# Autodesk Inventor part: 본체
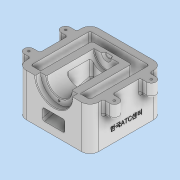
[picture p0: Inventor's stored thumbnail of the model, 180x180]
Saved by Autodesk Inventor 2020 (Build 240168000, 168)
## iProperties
Created: 2022-03
Part Number: 본체
Material: 일반
Document SubType Name: Modeling
Designer: Administrator
Density: 1 g/cm^3
Appearance: 기본값
Author: Administrator
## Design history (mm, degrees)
sketch "스케치1"
  geometry: L1 (55, 55)-(-55, 55); L2 (-55, 55)-(-55, -55); L3 (-55, -55)-(55, -55); L4 (55, -55)-(55, 55); L5 (55, 55)-(-55, -55); L6 (-55, 55)-(55, -55); 1 further point
  constraints: 12 end point, 2 midpoint, 2 parallel, 1 horizontal, 1 perpendicular
  dimensions: "d0" = 110 distance of L3.end L1.start; "d1" = 110 distance of L1.start L1.end
extrude "돌출1" new body sketch "스케치1" distance "d2" = 65; taper "d3" = 0 deg
sketch "스케치2"
  geometry: L1 (45, 65)-(45, 0); L2 (-55, 65)-(55, 65) reference; L3 (55, 0)-(55, 65) reference; L4 (-55, 0)-(55, 0) reference; L5 (33, 65)-(33, 30); L6 (33, 30)-(-45, 9.1); L7 (-45, 9.1)-(-45, 0); L8 (-55, 11.597)-(19, 31.425); L9 (19, 31.425)-(19, 65); L10 (-19, 65)-(-19, 38.843); L11 (-19, 38.843)-(-55, 29.197); L12 (-55, 0)-(-55, 65) reference; 2 further points
  constraints: 16 end point, 7 point on line, 3 vertical
  dimensions: "d4" = 22 distance between parallel lines of L3 L5; "d5" = 10 distance between parallel lines of L3 L1; "d6" = 30 distance from line of L4 L5.end; "d7" = 75 deg angle of L6 L5; "d8" = 10 distance from line of L4.start L7; "d29" = 5 distance between parallel lines of L6 L8; "d30" = 17 distance between parallel lines of L8 L11; "d37" = 36 distance between parallel lines of L12 L10; "d38" = 38 distance between parallel lines of L9 L10
sketch "스케치3"
  geometry: L1 (-55, 55)-(-55, -55) reference; L2 (55, -55)-(55, 55) reference; L3 (-55, 0)-(55, 0); L4 (55, 28)-(47, 28); L5 (47, 28)-(47, 19); L6 (47, 19)-(-25, 19); L7 (-25, 19)-(-25, 7.5); L8 (-25, 7.5)-(-29, 5.191); L9 (-29, 5.191)-(-29, 0); 1 further point
  constraints: 14 end point, 3 perpendicular, 2 midpoint, 2 point on line, 1 horizontal, 1 vertical
  dimensions: "d9" = 56 diameter of L4 L3; "d11" = 38 diameter of L6 L3; "d12" = 8 distance of L4.start L4.end; "d13" = 72 distance of L5.end L6.end; "d14" = 30 deg angle of L3 L8; "d15" = 4 distance between parallel lines of L7 L9; "d61" = 15 diameter of L7.end L3
revolve "회전1" sketch "스케치3" stored, may be unused: angle "d17" = 90 deg
sketch "스케치4"
  geometry: L1 (-35, -65)-(-35, -55); L2 (-21, -65)-(-21, -55); L3 (-55, -55)-(55, -55) reference; L4 (-55, 55)-(-55, -55) reference; A1 r 7 centre (-28, -65) between (-35, -65) and (-21, -65); 1 further point
  constraints: 4 end point, 2 point on circle, 2 point on line, 2 vertical, 1 centre point
  dimensions: "d18" = 14 diameter of A1; "d19" = 65 vertical distance of point (0, 0) A1.centre; "d42" = 27 distance from line of A1.centre L4
extrude "돌출2" join sketch "스케치4" distance "d20" = 20; taper "d21" = 0 deg
sketch "스케치5"
  geometry: A1 r 7 centre (-28, -65) between (-35, -65) and (-21, -65) reference; 2 further points
  constraints: 1 coincident
hole "구멍1" sketch "스케치5" at (-28, -65) diameter "d22" = 3.242; stored, may be unused: countersink angle "d26" = 90 deg, drill point angle "d28" = 118 deg; dims "d23" = 9, "d24" = 18, "d25" = 2, "d27" = 11
extrude "돌출3" cut sketch "스케치2" stored distance "d32" = 34; taper "d33" = 0 deg
extrude "돌출4" cut sketch "스케치2" stored distance "d34" = 90; taper "d35" = 0 deg
sketch "스케치6"
  geometry: L1 (-45, -45)-(45, -45) reference; L2 (-45, -30)-(45, -30); L3 (45, -30)-(45, -45); L4 (-45, -45)-(-45, 45) reference; 1 further point
  constraints: 4 end point, 1 parallel, 1 point on line, 1 vertical
  dimensions: "d36" = 15 distance between parallel lines of L1 L2
extrude "돌출5" cut sketch "스케치6" distance "d39" = 90; taper "d40" = 0 deg
fillet "모깎기1" dims "d41" = 1
fillet "모깎기2" dims "d43" = 13
fillet "모깎기3" dims "d44" = 3
sketch "스케치7"
  geometry: A1 r 28 centre (0, -19) between (0, -47) and (0, 9) reference; 2 further points
  constraints: 1 horizontal alignment
  dimensions: "d45" = 23 distance of A1.centre point (23, -19)
hole "구멍2" sketch "스케치7" at (23, -19) diameter "d46" = 3.242; stored, may be unused: countersink angle "d50" = 90 deg, drill point angle "d52" = 118 deg; dims "d47" = 9, "d48" = 18, "d49" = 2, "d51" = 11
fillet "모깎기4" dims "d53" = 3
chamfer "모따기1" distance "d54" = 1; stored, may be unused: second distance "d55" = 2, angle "d56" = 45 deg
sketch "스케치8"
  geometry: L1 (97, -65)-(97, 0) reference; 2 further points
  constraints: 1 other
  dimensions: "d57" = 20 distance of point (42, 0) point (42, -20); "d58" = 55 distance from line of point (42, -20) L1
feature "엠보싱1" sketch "스케치8" dims "d0" = 110, "d1" = 110, "d59" = 0.5, "d60" = 0
fillet "모깎기5" dims "d62" = 3
fillet "모깎기6" dims "d63" = 3
fillet "모깎기7" dims "d64" = 3
fillet "모깎기8" dims "d65" = 3
node "솔리드1"
mirror "미러1"
mirror "미러2"
mirror "미러3"
feature "A9D066F2-1C7D-4E18-AEED-F7BC21143FA4" dims "d22" = 3.242, "d23" = 9, "d24" = 18, "d25" = 2, "d26" = 90 deg, "d27" = 11, "d28" = 118 deg
